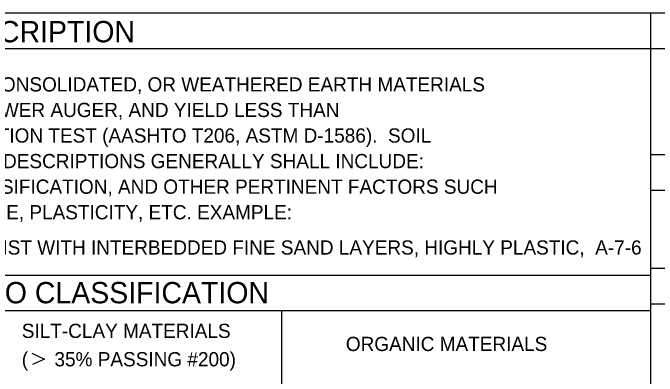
# Model space of a CAD drawing. Extents: x 278710 to 279187, y 171464 to 171625.
# Drawn here: x 279023.58 to 279043.27, y 171554.93 to 171566.02 of the extents above; entities that cross this region are included whole.
import ezdxf

# ---------------------------------------------------------------- set-up
doc = ezdxf.new("R2010")
doc.units = 0
doc.layers.add('Geotech Sheets and Borders Cell', color=7, linetype='Continuous')

msp = doc.modelspace()

# ---------------------------------------------------------------- linework, layer by layer
at = {"layer": 'Geotech Sheets and Borders Cell'}
for p, q in [((279005.33, 171566.02), (279158.027, 171566.02)), ((279043.07, 171566.02), (279043.07, 171485.806)), ((279005.33, 171564.936), (279158.027, 171564.936)), ((279081.678, 171561.682), (279043.07, 171561.682)), ((279081.678, 171560.598), (279043.07, 171560.598)), ((279081.678, 171558.212), (279043.07, 171558.212)), ((279005.33, 171558.017), (279043.07, 171558.017)), ((279081.678, 171557.127), (279043.07, 171557.127)), ((279005.33, 171556.932), (279043.07, 171556.932)), ((279031.791, 171556.932), (279031.791, 171537.446)), ((279031.791, 171556.932), (279031.791, 171552.486))]:
    msp.add_line(p, q, dxfattribs=at)
msp.add_lwpolyline([(279024.157, 171555.626), (279024.547, 171555.444), (279024.183, 171555.288)], dxfattribs=at)

# ---------------------------------------------------------------- texts
for s, height, p in [('SOIL DESCRIPTION', 0.6507, (279019.142, 171565.122)), ('SOIL IS CONSIDERED TO BE THE UNCONSOLIDATED,  SEMI-CONSOLIDATED, OR WEATHERED EARTH MATERIALS ', 0.43381, (279005.842, 171563.621)), ('THAT CAN BE PENETRATED WITH A CONTINUOUS FLIGHT POWER AUGER, AND YIELD LESS THAN ', 0.43381, (279005.842, 171562.84)), ('100 BLOWS PER FOOT ACCORDING TO STANDARD PENETRATION TEST (AASHTO T206, ASTM D-1586).  SOIL ', 0.43381, (279005.842, 171562.06)), ('CLASSIFICATION IS BASED ON THE AASHTO SYSTEM.  BASIC DESCRIPTIONS GENERALLY SHALL INCLUDE:', 0.43381, (279005.842, 171561.279)), ('CONSISTENCY, COLOR, TEXTURE, MOISTURE, AASHTO CLASSIFICATION, AND OTHER PERTINENT FACTORS SUCH ', 0.43381, (279005.842, 171560.498)), ('AS MINERALOGICAL COMPOSITION, ANGULARITY, STRUCTURE, PLASTICITY, ETC. EXAMPLE:', 0.43381, (279005.842, 171559.717)), ('VERY STIFF,  GRAY, SILTY CLAY,  MOIST WITH INTERBEDDED FINE SAND LAYERS, HIGHLY PLASTIC,  A-7-6', 0.43381, (279012.753, 171558.641)), ('SOIL LEGEND AND AASHTO CLASSIFICATION', 0.6507, (279012.31, 171557.153)), ('SILT-CLAY MATERIALS', 0.43381, (279023.853, 171556.095)), ('ORGANIC MATERIALS', 0.43381, (279033.757, 171555.696)), ('(     35% PASSING #200)', 0.43381, (279023.853, 171555.229))]:
    msp.add_text(s, height=height, dxfattribs=at).set_placement(p)

doc.saveas('drawing.dxf')
